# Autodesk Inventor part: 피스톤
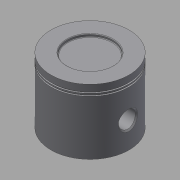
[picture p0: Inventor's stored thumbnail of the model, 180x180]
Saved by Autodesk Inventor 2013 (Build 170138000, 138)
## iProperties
Created: 2016-11
Part Number: 피스톤
Material: 강철, 탄소
Document SubType Name: Modeling
Designer: mduedu
Density: 7.87 g/cm^3
Mass: 273.399 g
Surface Area: 264.986 cm^2
Volume: 34.7394 cm^3
Author: mduedu
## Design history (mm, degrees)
sketch "스케치1"
  geometry: C1 r 30 at (0, 0); 1 further point
  constraints: 1 centre point, 1 coincident
  dimensions: "d0" = 60 diameter of C1
extrude "돌출1" new body sketch "스케치1" distance "d1" = 50; taper "d2" = 0 deg
sketch "스케치2"
  geometry: C1 r 28 at (0, 0); 1 further point
  constraints: 1 centre point, 1 coincident
  dimensions: "d3" = 56 diameter of C1
extrude "돌출2" cut sketch "스케치2" distance "d4" = 45; taper "d5" = 0 deg
sketch "스케치3"
  geometry: L1 (30, 0)-(30, 50) reference; L2 (30, 45)-(29, 45); L3 (29, 45)-(29, 44); L4 (29, 44)-(30, 44); L5 (30, 44)-(30, 45); L6 (30, 43)-(29, 43); L7 (29, 43)-(29, 42); L8 (29, 42)-(30, 42); L9 (30, 42)-(30, 43); L10 (30, 50)-(-30, 50) reference; L11 (0, 50)-(0, 0)
  constraints: 18 end point, 4 parallel, 3 equal length, 3 perpendicular, 2 horizontal, 2 point on line, 1 midpoint
  dimensions: "d6" = 1 distance of L2.start L2.end; "d8" = 5 distance between parallel lines of L10 L2; "d9" = 1 distance between parallel lines of L6 L4
revolve "회전1" sketch "스케치3" stored, may be unused: angle "d10" = 90 deg
node "작업 평면1"
sketch "스케치4"
  geometry: C1 r 10 at (20, 0); C2 r 6.5 at (20, 0); 1 further point
  constraints: 2 centre point, 1 coincident, 1 horizontal alignment
  dimensions: "d12" = 20 diameter of C1; "d13" = 13 diameter of C2; "d14" = 20 distance of point (0, 0) C1.centre
extrude "돌출3" join sketch "스케치4" stored distance "d15" = 11.75; taper "d16" = 0 deg
extrude "돌출4" cut sketch "스케치4" stored distance "d17" = 72; taper "d18" = 0 deg
fillet "모깎기1" dims "d19" = 3
fillet "모깎기2" dims "d20" = 3
chamfer "모따기1" distance "d21" = 1; stored, may be unused: second distance "d22" = 2, angle "d23" = 45 deg
chamfer "모따기2" distance "d24" = 1; stored, may be unused: second distance "d25" = 2, angle "d26" = 45 deg
sketch "스케치5"
  geometry: C1 r 17.5 at (0, 0); 1 further point
  constraints: 1 centre point, 1 coincident
  dimensions: "d27" = 35 diameter of C1
extrude "돌출5" cut sketch "스케치5" distance "d28" = 2; taper "d29" = 0 deg
fillet "모깎기3" dims "d30" = 0.5
node "솔리드1"
mirror "대칭1"
